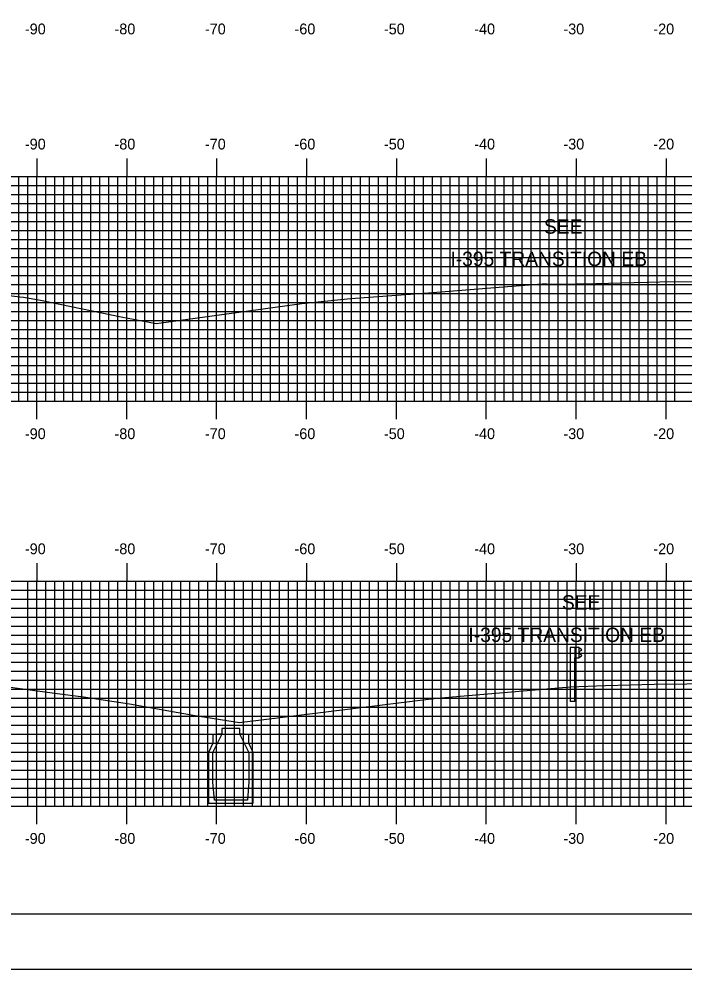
# Model space of a CAD drawing. Extents: x 843356 to 843699, y 363538 to 363758.
# Drawn here: x 843429.4 to 843503.4, y 363537.6 to 363643.2 of the extents above; entities that cross this region are included whole.
import ezdxf

# ---------------------------------------------------------------- set-up
doc = ezdxf.new("R2010")
doc.units = 0
for name, color, linetype in [('ANNOTATION', 7, 'Continuous'), ('BORDER', 7, 'Continuous'), ('H_V ANNOTATION', 7, 'Continuous'), ('M_Guardrail', 7, 'Continuous'), ('MAJOR', 7, 'Continuous'), ('MINOR', 7, 'Continuous'), ('PLOT BOUNDARY', 7, 'Continuous'), ('S_Drainage_CB', 7, 'Continuous'), ('S_Roadway_Centerline', 7, 'Continuous')]:
    doc.layers.add(name, color=color, linetype=linetype)

msp = doc.modelspace()

# ---------------------------------------------------------------- linework, layer by layer
at = {"layer": 'BORDER'}
msp.add_lwpolyline([(843371.82, 363543.72), (843691.82, 363543.72), (843691.82, 363753.72), (843371.82, 363753.72)], close=True, dxfattribs=at)
at = {"layer": 'M_Guardrail'}
for p, q in [((843490.77, 363573.36), (843490.77, 363567.36)), ((843491.27, 363573.36), (843490.77, 363573.36)), ((843491.76, 363573.36), (843491.27, 363573.36)), ((843491.27, 363573.36), (843491.27, 363572.19)), ((843491.76, 363572.19), (843491.76, 363573.36)), ((843491.76, 363573.29), (843491.84, 363573.27)), ((843491.77, 363572.82), (843491.77, 363572.73)), ((843492, 363573.02), (843491.8, 363572.89)), ((843491.8, 363572.67), (843492, 363572.53)), ((843491.85, 363573.27), (843492, 363573.17)), ((843491.27, 363567.36), (843491.27, 363572.19)), ((843491.27, 363572.19), (843491.76, 363572.19)), ((843491.84, 363572.28), (843491.76, 363572.27)), ((843492, 363572.39), (843491.85, 363572.29)), ((843491.27, 363567.36), (843490.77, 363567.36))]:
    msp.add_line(p, q, dxfattribs=at)
for centre, major_axis, start_param, end_param in [((843491.85, 363572.82), (-0.0789, 0), 5.323254, 6.283185), ((843491.85, 363572.73), (-0.0789, 0), 6.283185, 7.243116), ((843491.83, 363573.23), (0.0417, 0), 0.959931, 1.396263), ((843491.95, 363573.09), (0.0877, 0), 5.323254, 7.243116), ((843491.83, 363572.32), (0.0417, 0), 4.886922, 5.323254), ((843491.95, 363572.46), (0.0877, 0), 5.323254, 7.243116)]:
    msp.add_ellipse(centre, major_axis=major_axis, ratio=0.995501, start_param=start_param, end_param=end_param, dxfattribs=at)
at = {"layer": 'MAJOR'}
for p, q in [((843431.42, 363627.73), (843431.42, 363625.72)), ((843441.42, 363627.73), (843441.42, 363625.72)), ((843451.42, 363627.73), (843451.42, 363625.72)), ((843461.42, 363627.73), (843461.42, 363625.72)), ((843471.42, 363627.73), (843471.42, 363625.72)), ((843481.42, 363627.73), (843481.42, 363625.72)), ((843491.42, 363627.73), (843491.42, 363625.72)), ((843501.42, 363627.73), (843501.42, 363625.72)), ((843381.42, 363625.72), (843661.42, 363625.72)), ((843381.42, 363625.72), (843661.42, 363625.72)), ((843431.42, 363600.72), (843431.42, 363625.72)), ((843441.42, 363600.72), (843441.42, 363625.72)), ((843451.42, 363600.72), (843451.42, 363625.72)), ((843461.42, 363600.72), (843461.42, 363625.72)), ((843471.42, 363600.72), (843471.42, 363625.72)), ((843481.42, 363600.72), (843481.42, 363625.72)), ((843491.42, 363600.72), (843491.42, 363625.72)), ((843501.42, 363600.72), (843501.42, 363625.72)), ((843381.42, 363620.72), (843661.42, 363620.72)), ((843381.42, 363615.72), (843661.42, 363615.72)), ((843381.42, 363610.72), (843661.42, 363610.72)), ((843381.42, 363605.72), (843661.42, 363605.72)), ((843381.42, 363600.72), (843661.42, 363600.72)), ((843381.42, 363600.72), (843661.42, 363600.72)), ((843431.42, 363598.72), (843431.42, 363600.72)), ((843441.42, 363598.72), (843441.42, 363600.72)), ((843451.42, 363598.72), (843451.42, 363600.72)), ((843461.42, 363598.72), (843461.42, 363600.72)), ((843471.42, 363598.72), (843471.42, 363600.72)), ((843481.42, 363598.72), (843481.42, 363600.72)), ((843491.42, 363598.72), (843491.42, 363600.72)), ((843501.42, 363598.72), (843501.42, 363600.72)), ((843431.42, 363582.73), (843431.42, 363580.72)), ((843441.42, 363582.73), (843441.42, 363580.72)), ((843451.42, 363582.73), (843451.42, 363580.72)), ((843461.42, 363582.73), (843461.42, 363580.72)), ((843471.42, 363582.73), (843471.42, 363580.72)), ((843481.42, 363582.73), (843481.42, 363580.72)), ((843491.42, 363582.73), (843491.42, 363580.72)), ((843501.42, 363582.73), (843501.42, 363580.72)), ((843381.42, 363580.72), (843661.42, 363580.72)), ((843381.42, 363580.72), (843661.42, 363580.72)), ((843431.42, 363555.72), (843431.42, 363580.72)), ((843441.42, 363555.72), (843441.42, 363580.72)), ((843451.42, 363555.72), (843451.42, 363580.72)), ((843461.42, 363555.72), (843461.42, 363580.72)), ((843471.42, 363555.72), (843471.42, 363580.72)), ((843481.42, 363555.72), (843481.42, 363580.72)), ((843491.42, 363555.72), (843491.42, 363580.72)), ((843501.42, 363555.72), (843501.42, 363580.72)), ((843381.42, 363575.72), (843661.42, 363575.72)), ((843381.42, 363570.72), (843661.42, 363570.72)), ((843381.42, 363565.72), (843661.42, 363565.72)), ((843381.42, 363560.72), (843661.42, 363560.72)), ((843381.42, 363555.72), (843661.42, 363555.72)), ((843381.42, 363555.72), (843661.42, 363555.72)), ((843431.42, 363553.72), (843431.42, 363555.72)), ((843441.42, 363553.72), (843441.42, 363555.72)), ((843451.42, 363553.72), (843451.42, 363555.72)), ((843461.42, 363553.72), (843461.42, 363555.72)), ((843471.42, 363553.72), (843471.42, 363555.72)), ((843481.42, 363553.72), (843481.42, 363555.72)), ((843491.42, 363553.72), (843491.42, 363555.72)), ((843501.42, 363553.72), (843501.42, 363555.72))]:
    msp.add_line(p, q, dxfattribs=at)
at = {"layer": 'MINOR'}
for p, q in [((843429.42, 363600.72), (843429.42, 363625.72)), ((843430.42, 363600.72), (843430.42, 363625.72)), ((843432.42, 363600.72), (843432.42, 363625.72)), ((843433.42, 363600.72), (843433.42, 363625.72)), ((843434.42, 363600.72), (843434.42, 363625.72)), ((843435.42, 363600.72), (843435.42, 363625.72)), ((843436.42, 363600.72), (843436.42, 363625.72)), ((843437.42, 363600.72), (843437.42, 363625.72)), ((843438.42, 363600.72), (843438.42, 363625.72)), ((843439.42, 363600.72), (843439.42, 363625.72)), ((843440.42, 363600.72), (843440.42, 363625.72)), ((843442.42, 363600.72), (843442.42, 363625.72)), ((843443.42, 363600.72), (843443.42, 363625.72)), ((843444.42, 363600.72), (843444.42, 363625.72)), ((843445.42, 363600.72), (843445.42, 363625.72)), ((843446.42, 363600.72), (843446.42, 363625.72)), ((843447.42, 363600.72), (843447.42, 363625.72)), ((843448.42, 363600.72), (843448.42, 363625.72)), ((843449.42, 363600.72), (843449.42, 363625.72)), ((843450.42, 363600.72), (843450.42, 363625.72)), ((843452.42, 363600.72), (843452.42, 363625.72)), ((843453.42, 363600.72), (843453.42, 363625.72)), ((843454.42, 363600.72), (843454.42, 363625.72)), ((843455.42, 363600.72), (843455.42, 363625.72)), ((843456.42, 363600.72), (843456.42, 363625.72)), ((843457.42, 363600.72), (843457.42, 363625.72)), ((843458.42, 363600.72), (843458.42, 363625.72)), ((843459.42, 363600.72), (843459.42, 363625.72)), ((843460.42, 363600.72), (843460.42, 363625.72)), ((843462.42, 363600.72), (843462.42, 363625.72)), ((843463.42, 363600.72), (843463.42, 363625.72)), ((843464.42, 363600.72), (843464.42, 363625.72)), ((843465.42, 363600.72), (843465.42, 363625.72)), ((843466.42, 363600.72), (843466.42, 363625.72)), ((843467.42, 363600.72), (843467.42, 363625.72)), ((843468.42, 363600.72), (843468.42, 363625.72)), ((843469.42, 363600.72), (843469.42, 363625.72)), ((843470.42, 363600.72), (843470.42, 363625.72)), ((843472.42, 363600.72), (843472.42, 363625.72)), ((843473.42, 363600.72), (843473.42, 363625.72)), ((843474.42, 363600.72), (843474.42, 363625.72)), ((843475.42, 363600.72), (843475.42, 363625.72)), ((843476.42, 363600.72), (843476.42, 363625.72)), ((843477.42, 363600.72), (843477.42, 363625.72)), ((843478.42, 363600.72), (843478.42, 363625.72)), ((843479.42, 363600.72), (843479.42, 363625.72)), ((843480.42, 363600.72), (843480.42, 363625.72)), ((843482.42, 363600.72), (843482.42, 363625.72)), ((843483.42, 363600.72), (843483.42, 363625.72)), ((843484.42, 363600.72), (843484.42, 363625.72)), ((843485.42, 363600.72), (843485.42, 363625.72)), ((843486.42, 363600.72), (843486.42, 363625.72)), ((843487.42, 363600.72), (843487.42, 363625.72)), ((843488.42, 363600.72), (843488.42, 363625.72)), ((843489.42, 363600.72), (843489.42, 363625.72)), ((843490.42, 363600.72), (843490.42, 363625.72)), ((843492.42, 363600.72), (843492.42, 363625.72)), ((843493.42, 363600.72), (843493.42, 363625.72)), ((843494.42, 363600.72), (843494.42, 363625.72)), ((843495.42, 363600.72), (843495.42, 363625.72)), ((843496.42, 363600.72), (843496.42, 363625.72)), ((843497.42, 363600.72), (843497.42, 363625.72)), ((843498.42, 363600.72), (843498.42, 363625.72)), ((843499.42, 363600.72), (843499.42, 363625.72)), ((843500.42, 363600.72), (843500.42, 363625.72)), ((843502.42, 363600.72), (843502.42, 363625.72)), ((843381.42, 363624.72), (843661.42, 363624.72)), ((843381.42, 363623.72), (843661.42, 363623.72)), ((843381.42, 363622.72), (843661.42, 363622.72)), ((843381.42, 363621.72), (843661.42, 363621.72)), ((843381.42, 363619.72), (843661.42, 363619.72)), ((843381.42, 363618.72), (843661.42, 363618.72)), ((843381.42, 363617.72), (843661.42, 363617.72)), ((843381.42, 363616.72), (843661.42, 363616.72)), ((843381.42, 363614.72), (843661.42, 363614.72)), ((843381.42, 363613.72), (843661.42, 363613.72)), ((843381.42, 363612.72), (843661.42, 363612.72)), ((843381.42, 363611.72), (843661.42, 363611.72)), ((843381.42, 363609.72), (843661.42, 363609.72)), ((843381.42, 363608.72), (843661.42, 363608.72)), ((843381.42, 363607.72), (843661.42, 363607.72)), ((843381.42, 363606.72), (843661.42, 363606.72)), ((843381.42, 363604.72), (843661.42, 363604.72)), ((843381.42, 363603.72), (843661.42, 363603.72)), ((843381.42, 363602.72), (843661.42, 363602.72)), ((843381.42, 363601.72), (843661.42, 363601.72)), ((843430.42, 363555.72), (843430.42, 363580.72)), ((843432.42, 363555.72), (843432.42, 363580.72)), ((843433.42, 363555.72), (843433.42, 363580.72)), ((843434.42, 363555.72), (843434.42, 363580.72)), ((843435.42, 363555.72), (843435.42, 363580.72)), ((843436.42, 363555.72), (843436.42, 363580.72)), ((843437.42, 363555.72), (843437.42, 363580.72)), ((843438.42, 363555.72), (843438.42, 363580.72)), ((843439.42, 363555.72), (843439.42, 363580.72)), ((843440.42, 363555.72), (843440.42, 363580.72)), ((843442.42, 363555.72), (843442.42, 363580.72)), ((843443.42, 363555.72), (843443.42, 363580.72)), ((843444.42, 363555.72), (843444.42, 363580.72)), ((843445.42, 363555.72), (843445.42, 363580.72)), ((843446.42, 363555.72), (843446.42, 363580.72)), ((843447.42, 363555.72), (843447.42, 363580.72)), ((843448.42, 363555.72), (843448.42, 363580.72)), ((843449.42, 363555.72), (843449.42, 363580.72)), ((843450.42, 363555.72), (843450.42, 363580.72)), ((843452.42, 363555.72), (843452.42, 363580.72)), ((843453.42, 363555.72), (843453.42, 363580.72)), ((843454.42, 363555.72), (843454.42, 363580.72)), ((843455.42, 363555.72), (843455.42, 363580.72)), ((843456.42, 363555.72), (843456.42, 363580.72)), ((843457.42, 363555.72), (843457.42, 363580.72)), ((843458.42, 363555.72), (843458.42, 363580.72)), ((843459.42, 363555.72), (843459.42, 363580.72)), ((843460.42, 363555.72), (843460.42, 363580.72)), ((843462.42, 363555.72), (843462.42, 363580.72)), ((843463.42, 363555.72), (843463.42, 363580.72)), ((843464.42, 363555.72), (843464.42, 363580.72)), ((843465.42, 363555.72), (843465.42, 363580.72)), ((843466.42, 363555.72), (843466.42, 363580.72)), ((843467.42, 363555.72), (843467.42, 363580.72)), ((843468.42, 363555.72), (843468.42, 363580.72)), ((843469.42, 363555.72), (843469.42, 363580.72)), ((843470.42, 363555.72), (843470.42, 363580.72)), ((843472.42, 363555.72), (843472.42, 363580.72)), ((843473.42, 363555.72), (843473.42, 363580.72)), ((843474.42, 363555.72), (843474.42, 363580.72)), ((843475.42, 363555.72), (843475.42, 363580.72)), ((843476.42, 363555.72), (843476.42, 363580.72)), ((843477.42, 363555.72), (843477.42, 363580.72)), ((843478.42, 363555.72), (843478.42, 363580.72)), ((843479.42, 363555.72), (843479.42, 363580.72)), ((843480.42, 363555.72), (843480.42, 363580.72)), ((843482.42, 363555.72), (843482.42, 363580.72)), ((843483.42, 363555.72), (843483.42, 363580.72)), ((843484.42, 363555.72), (843484.42, 363580.72)), ((843485.42, 363555.72), (843485.42, 363580.72)), ((843486.42, 363555.72), (843486.42, 363580.72)), ((843487.42, 363555.72), (843487.42, 363580.72)), ((843488.42, 363555.72), (843488.42, 363580.72)), ((843489.42, 363555.72), (843489.42, 363580.72)), ((843490.42, 363555.72), (843490.42, 363580.72)), ((843492.42, 363555.72), (843492.42, 363580.72)), ((843493.42, 363555.72), (843493.42, 363580.72)), ((843494.42, 363555.72), (843494.42, 363580.72)), ((843495.42, 363555.72), (843495.42, 363580.72)), ((843496.42, 363555.72), (843496.42, 363580.72)), ((843497.42, 363555.72), (843497.42, 363580.72)), ((843498.42, 363555.72), (843498.42, 363580.72)), ((843499.42, 363555.72), (843499.42, 363580.72)), ((843500.42, 363555.72), (843500.42, 363580.72)), ((843502.42, 363555.72), (843502.42, 363580.72)), ((843503.42, 363555.72), (843503.42, 363580.72)), ((843381.42, 363579.72), (843661.42, 363579.72)), ((843381.42, 363578.72), (843661.42, 363578.72)), ((843381.42, 363577.72), (843661.42, 363577.72)), ((843381.42, 363576.72), (843661.42, 363576.72)), ((843381.42, 363574.72), (843661.42, 363574.72)), ((843381.42, 363573.72), (843661.42, 363573.72)), ((843381.42, 363572.72), (843661.42, 363572.72)), ((843381.42, 363571.72), (843661.42, 363571.72)), ((843381.42, 363569.72), (843661.42, 363569.72)), ((843381.42, 363568.72), (843661.42, 363568.72)), ((843381.42, 363567.72), (843661.42, 363567.72)), ((843381.42, 363566.72), (843661.42, 363566.72)), ((843381.42, 363564.72), (843661.42, 363564.72)), ((843381.42, 363563.72), (843661.42, 363563.72)), ((843381.42, 363562.72), (843661.42, 363562.72)), ((843381.42, 363561.72), (843661.42, 363561.72)), ((843381.42, 363559.72), (843661.42, 363559.72)), ((843381.42, 363558.72), (843661.42, 363558.72)), ((843381.42, 363557.72), (843661.42, 363557.72)), ((843381.42, 363556.72), (843661.42, 363556.72))]:
    msp.add_line(p, q, dxfattribs=at)
at = {"layer": 'PLOT BOUNDARY'}
msp.add_lwpolyline([(843355.64, 363537.6), (843695.64, 363537.6), (843695.64, 363757.6), (843355.64, 363757.6)], close=True, dxfattribs=at)
at = {"layer": 'S_Drainage_CB'}
for p, q in [((843451.99, 363563.69), (843451.01, 363563.69)), ((843451.01, 363563.69), (843451.01, 363562.7)), ((843451.01, 363561.68), (843451.99, 363563.69)), ((843455.01, 363563.69), (843454, 363563.69)), ((843454, 363563.69), (843455.01, 363561.68)), ((843455.01, 363562.7), (843455.01, 363563.69)), ((843451.01, 363562.7), (843450.52, 363561.68)), ((843455.5, 363561.68), (843455.01, 363562.7)), ((843450.52, 363561.68), (843450.52, 363556.04)), ((843451.01, 363558.37), (843451.01, 363561.68)), ((843455.01, 363561.68), (843455.01, 363558.37)), ((843455.5, 363556.04), (843455.5, 363561.68)), ((843451.17, 363556.37), (843451.01, 363558.37)), ((843455.01, 363558.37), (843454.85, 363556.37)), ((843450.52, 363556.04), (843455.5, 363556.04)), ((843454.85, 363556.37), (843451.17, 363556.37))]:
    msp.add_line(p, q, dxfattribs=at)
msp.add_lwpolyline([(843454.49, 363563.73), (843454, 363563.73), (843454, 363564.35), (843451.99, 363564.35), (843451.99, 363563.73), (843451.5, 363563.73)], dxfattribs=at)
at = {"layer": 'S_Roadway_Centerline'}
for points in [[(843415.78, 363614.06), (843429.52, 363612.34), (843429.93, 363612.3), (843431.83, 363611.97), (843440.79, 363610.12), (843444.7, 363609.36), (843445.26, 363609.46), (843460.91, 363611.58), (843466.3, 363612.15), (843474.5, 363612.74), (843484.26, 363613.52), (843487.65, 363613.77), (843488.17, 363613.77), (843489.18, 363613.75), (843493.6, 363613.82), (843500.73, 363614.01), (843508.07, 363614.08)], [(843427.36, 363569.07), (843433.66, 363568.22), (843436.6, 363567.85), (843441.73, 363567.07), (843448.8, 363565.82), (843453.97, 363565.02), (843454.21, 363565.04), (843455.77, 363565.22), (843474.06, 363567.48), (843475.97, 363567.72), (843478.95, 363567.98), (843490.78, 363568.97), (843491.72, 363569.01), (843494.68, 363569.13), (843500.12, 363569.26), (843507.38, 363569.35)]]:
    msp.add_lwpolyline(points, dxfattribs=at)

# ---------------------------------------------------------------- texts
at = {"layer": 'ANNOTATION'}
for s, p in [('SEE', (843487.84, 363619.36)), ('I-395 TRANSITION EB', (843477.43, 363615.76)), ('SEE', (843489.84, 363577.56)), ('I-395 TRANSITION EB', (843479.43, 363573.96))]:
    msp.add_text(s, height=1.6, dxfattribs=at).set_placement(p)
at = {"layer": 'H_V ANNOTATION'}
for s, p in [('-90', (843430.08, 363641.52)), ('-80', (843440.05, 363641.52)), ('-70', (843450.11, 363641.52)), ('-60', (843460.08, 363641.52)), ('-50', (843470.03, 363641.52)), ('-40', (843480.08, 363641.52)), ('-30', (843490, 363641.52)), ('-20', (843500.01, 363641.52)), ('-90', (843430.08, 363628.72)), ('-80', (843440.05, 363628.72)), ('-70', (843450.11, 363628.72)), ('-60', (843460.08, 363628.72)), ('-50', (843470.03, 363628.72)), ('-40', (843480.08, 363628.72)), ('-30', (843490, 363628.72)), ('-20', (843500.01, 363628.72)), ('-90', (843430.08, 363596.52)), ('-80', (843440.05, 363596.52)), ('-70', (843450.11, 363596.52)), ('-60', (843460.08, 363596.52)), ('-50', (843470.03, 363596.52)), ('-40', (843480.08, 363596.52)), ('-30', (843490, 363596.52)), ('-20', (843500.01, 363596.52)), ('-90', (843430.08, 363583.72)), ('-80', (843440.05, 363583.72)), ('-70', (843450.11, 363583.72)), ('-60', (843460.08, 363583.72)), ('-50', (843470.03, 363583.72)), ('-40', (843480.08, 363583.72)), ('-30', (843490, 363583.72)), ('-20', (843500.01, 363583.72)), ('-90', (843430.08, 363551.52)), ('-80', (843440.05, 363551.52)), ('-70', (843450.11, 363551.52)), ('-60', (843460.08, 363551.52)), ('-50', (843470.03, 363551.52)), ('-40', (843480.08, 363551.52)), ('-30', (843490, 363551.52)), ('-20', (843500.01, 363551.52))]:
    msp.add_text(s, height=1.2, dxfattribs=at).set_placement(p)

doc.saveas('drawing.dxf')
